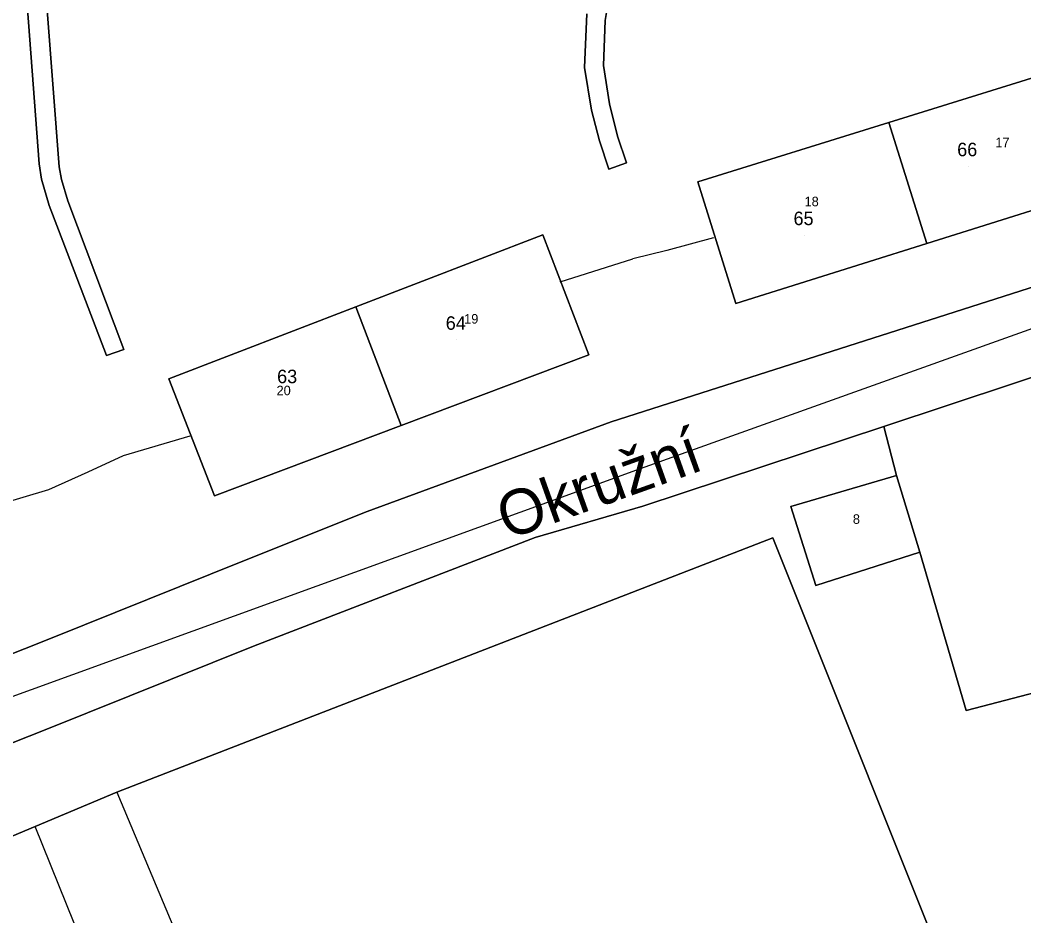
# Model space of a CAD drawing. Extents: x -873642 to -872917, y -1012962 to -1012567.
# Drawn here: x -873373.1 to -873283.8, y -1012828.2 to -1012748.5 of the extents above; entities that cross this region are included whole.
import ezdxf

# ---------------------------------------------------------------- set-up
doc = ezdxf.new("R2010")
doc.units = 0
for name, color, linetype in [('adresni_misto', 7, 'Continuous'), ('cisla_parcelni_kn', 7, 'Continuous'), ('cislo_domovni', 7, 'Continuous'), ('osy_ulic', 7, 'Continuous'), ('parcely_kn', 7, 'Continuous'), ('stavebni_objekty_bydleni', 7, 'Continuous'), ('stavebni_objekty_vyroba', 7, 'Continuous'), ('TRASY - zamereno', 7, 'Continuous'), ('ulice', 7, 'Continuous')]:
    doc.layers.add(name, color=color, linetype=linetype)

msp = doc.modelspace()

# ---------------------------------------------------------------- linework, layer by layer
at = {"layer": 'adresni_misto'}
for p, q in [((-873288.69, -1012761.56), (-873288.69, -1012761.56)), ((-873303.25, -1012767.69), (-873303.25, -1012767.69)), ((-873334.19, -1012777), (-873334.19, -1012777)), ((-873349.19, -1012781.75), (-873349.19, -1012781.75))]:
    msp.add_line(p, q, dxfattribs=at)
at = {"layer": 'osy_ulic'}
msp.add_lwpolyline([(-873411.85, -1012822.53), (-873317.85, -1012788.44), (-873277.23, -1012773.91), (-873252.76, -1012767.01), (-873201.18, -1012755.57), (-873115.6, -1012739.3), (-873104.65, -1012731.3), (-873088.93, -1012706.26), (-873080.41, -1012681.66), (-873071.61, -1012653.78), (-873070.57, -1012650.45), (-873066.08, -1012632.13), (-873063.74, -1012625.63), (-873059.56, -1012597.3)], dxfattribs=at)
at = {"layer": 'parcely_kn'}
for points in [[(-873320.46, -1012784.28), (-873268.07, -1012767.54), (-873249.92, -1012762.57), (-873226.73, -1012756.94), (-873186.64, -1012748.89), (-873149.68, -1012742.06), (-873135.84, -1012739.52), (-873124.72, -1012736.51), (-873113.32, -1012731.6), (-873103.81, -1012724.84), (-873095.71, -1012715.02), (-873089.72, -1012704.46), (-873086.77, -1012695.86), (-873085.73, -1012692.85), (-873081.52, -1012670.94), (-873077.58, -1012656.47), (-873075.63, -1012649.79), (-873072.81, -1012640.75), (-873068.46, -1012627.76), (-873067.09, -1012621.71)], [(-873320.46, -1012784.28), (-873268.07, -1012767.54), (-873249.92, -1012762.57), (-873226.73, -1012756.94), (-873186.64, -1012748.89), (-873149.68, -1012742.06), (-873135.84, -1012739.52), (-873124.72, -1012736.51), (-873113.32, -1012731.6), (-873103.81, -1012724.84), (-873095.71, -1012715.02), (-873089.72, -1012704.46), (-873086.77, -1012695.86), (-873085.73, -1012692.85), (-873081.52, -1012670.94), (-873077.58, -1012656.47), (-873075.63, -1012649.79), (-873072.81, -1012640.75), (-873068.46, -1012627.76), (-873067.09, -1012621.71)], [(-873492.26, -1012636.3), (-873470.15, -1012634.51), (-873474.09, -1012635.88), (-873476.25, -1012638.16), (-873476.91, -1012642.49), (-873474.55, -1012659.21), (-873473.95, -1012664.84), (-873471.34, -1012679.34), (-873470.31, -1012685.53), (-873467.35, -1012700.29), (-873461.39, -1012719.27), (-873456.13, -1012732.5), (-873430.5, -1012781.58), (-873414.44, -1012810.45), (-873408.91, -1012815.19), (-873407.03, -1012815.83), (-873405.77, -1012816.17), (-873403.3, -1012816.28), (-873400.05, -1012815.37), (-873370.19, -1012803.49), (-873353.25, -1012796.68), (-873342.17, -1012792.27), (-873320.46, -1012784.28)], [(-873492.26, -1012636.3), (-873470.15, -1012634.51), (-873474.09, -1012635.88), (-873476.25, -1012638.16), (-873476.91, -1012642.49), (-873474.55, -1012659.21), (-873473.95, -1012664.84), (-873471.34, -1012679.34), (-873470.31, -1012685.53), (-873467.35, -1012700.29), (-873461.39, -1012719.27), (-873456.13, -1012732.5), (-873430.5, -1012781.58), (-873414.44, -1012810.45), (-873408.91, -1012815.19), (-873407.03, -1012815.83), (-873405.77, -1012816.17), (-873403.3, -1012816.28), (-873400.05, -1012815.37), (-873370.19, -1012803.49), (-873353.25, -1012796.68), (-873342.17, -1012792.27), (-873320.46, -1012784.28)], [(-873267.15, -1012775.08), (-873296.21, -1012784.7), (-873317.65, -1012791.79), (-873327.22, -1012794.59), (-873352.28, -1012804.24), (-873370.67, -1012811.62), (-873407.44, -1012826.19), (-873420.81, -1012815.05), (-873432.2, -1012793.89), (-873433.76, -1012792.56), (-873435.3, -1012792.45), (-873437.28, -1012792.66), (-873438.97, -1012789.6), (-873437.44, -1012788.27), (-873436.61, -1012786.86), (-873438.55, -1012783.17), (-873447.85, -1012766.32), (-873454.18, -1012754.58), (-873460.09, -1012742.48), (-873462.37, -1012737.41), (-873469.44, -1012722.44), (-873475.56, -1012699.33), (-873477.8, -1012685.05)], [(-873267.15, -1012775.08), (-873296.21, -1012784.7), (-873317.65, -1012791.79), (-873327.22, -1012794.59), (-873352.28, -1012804.24), (-873370.67, -1012811.62), (-873407.44, -1012826.19), (-873420.81, -1012815.05), (-873432.2, -1012793.89), (-873433.76, -1012792.56), (-873435.3, -1012792.45), (-873437.28, -1012792.66), (-873438.97, -1012789.6), (-873437.44, -1012788.27), (-873436.61, -1012786.86), (-873438.55, -1012783.17), (-873447.85, -1012766.32), (-873454.18, -1012754.58), (-873460.09, -1012742.48), (-873462.37, -1012737.41), (-873469.44, -1012722.44), (-873475.56, -1012699.33), (-873477.8, -1012685.05)], [(-873372.72, -1012743.18), (-873371.35, -1012761.35), (-873371.16, -1012762.69), (-873370.48, -1012765.05), (-873369.65, -1012767.21), (-873365.37, -1012778.38), (-873363.83, -1012777.84), (-873368.81, -1012764.64), (-873369.36, -1012762.74), (-873369.57, -1012761.6), (-873371.72, -1012733.69)], [(-873371.72, -1012733.69), (-873369.57, -1012761.6), (-873369.36, -1012762.74), (-873368.81, -1012764.64), (-873363.83, -1012777.84), (-873365.37, -1012778.38), (-873369.65, -1012767.21), (-873370.48, -1012765.05), (-873371.16, -1012762.69), (-873371.35, -1012761.35), (-873372.72, -1012743.18)], [(-873372.72, -1012743.18), (-873371.35, -1012761.35), (-873371.16, -1012762.69), (-873370.48, -1012765.05), (-873369.65, -1012767.21), (-873365.37, -1012778.38), (-873363.83, -1012777.84), (-873368.81, -1012764.64), (-873369.36, -1012762.74), (-873369.57, -1012761.6), (-873371.72, -1012733.69)], [(-873371.72, -1012733.69), (-873369.57, -1012761.6), (-873369.36, -1012762.74), (-873368.81, -1012764.64), (-873363.83, -1012777.84), (-873365.37, -1012778.38), (-873369.65, -1012767.21), (-873370.48, -1012765.05), (-873371.16, -1012762.69), (-873371.35, -1012761.35), (-873372.72, -1012743.18)], [(-873322.63, -1012747.98), (-873322.84, -1012752.76), (-873322.22, -1012756.56), (-873321.51, -1012759.3), (-873320.68, -1012761.82), (-873319.1, -1012761.25), (-873319.91, -1012758.89), (-873320.61, -1012755.99), (-873321.15, -1012752.59), (-873321.02, -1012748.59), (-873320.43, -1012745.18)], [(-873320.43, -1012745.18), (-873321.02, -1012748.59), (-873321.15, -1012752.59), (-873320.61, -1012755.99), (-873319.91, -1012758.89), (-873319.1, -1012761.25), (-873320.68, -1012761.82), (-873321.51, -1012759.3), (-873322.22, -1012756.56), (-873322.84, -1012752.76), (-873322.63, -1012747.98)], [(-873322.63, -1012747.98), (-873322.84, -1012752.76), (-873322.22, -1012756.56), (-873321.51, -1012759.3), (-873320.68, -1012761.82), (-873319.1, -1012761.25), (-873319.91, -1012758.89), (-873320.61, -1012755.99), (-873321.15, -1012752.59), (-873321.02, -1012748.59), (-873320.43, -1012745.18)], [(-873320.43, -1012745.18), (-873321.02, -1012748.59), (-873321.15, -1012752.59), (-873320.61, -1012755.99), (-873319.91, -1012758.89), (-873319.1, -1012761.25), (-873320.68, -1012761.82), (-873321.51, -1012759.3), (-873322.22, -1012756.56), (-873322.84, -1012752.76), (-873322.63, -1012747.98)], [(-873491.56, -1012871.97), (-873407.44, -1012826.19), (-873370.67, -1012811.62), (-873352.28, -1012804.24), (-873327.22, -1012794.59), (-873317.65, -1012791.79), (-873296.21, -1012784.7), (-873295.08, -1012789.07), (-873304.48, -1012791.83), (-873302.28, -1012798.85), (-873296.89, -1012797.13), (-873293, -1012795.88), (-873288.89, -1012809.97), (-873206.66, -1012788.54), (-873209.55, -1012779.29), (-873212.49, -1012767.05), (-873213.62, -1012762.14), (-873185.58, -1012756.25), (-873148.18, -1012749.22)], [(-873491.56, -1012871.97), (-873407.44, -1012826.19), (-873370.67, -1012811.62), (-873352.28, -1012804.24), (-873327.22, -1012794.59), (-873317.65, -1012791.79), (-873296.21, -1012784.7), (-873295.08, -1012789.07), (-873304.48, -1012791.83), (-873302.28, -1012798.85), (-873296.89, -1012797.13), (-873293, -1012795.88), (-873288.89, -1012809.97), (-873206.66, -1012788.54), (-873209.55, -1012779.29), (-873212.49, -1012767.05), (-873213.62, -1012762.14), (-873185.58, -1012756.25), (-873148.18, -1012749.22)], [(-873268.07, -1012767.54), (-873320.46, -1012784.28), (-873342.17, -1012792.27), (-873353.25, -1012796.68), (-873370.19, -1012803.49), (-873400.05, -1012815.37)], [(-873268.07, -1012767.54), (-873320.46, -1012784.28), (-873342.17, -1012792.27), (-873353.25, -1012796.68), (-873370.19, -1012803.49), (-873400.05, -1012815.37)]]:
    msp.add_lwpolyline(points, dxfattribs=at)
for points in [[(-873275.41, -1012763.1), (-873278.77, -1012752.39), (-873295.77, -1012757.66), (-873312.76, -1012762.93), (-873309.38, -1012773.75), (-873292.4, -1012768.43)], [(-873275.41, -1012763.1), (-873278.77, -1012752.39), (-873295.77, -1012757.66), (-873312.76, -1012762.93), (-873309.38, -1012773.75), (-873292.4, -1012768.43)], [(-873295.77, -1012757.66), (-873278.77, -1012752.39), (-873275.41, -1012763.1), (-873292.4, -1012768.43)], [(-873295.77, -1012757.66), (-873278.77, -1012752.39), (-873275.41, -1012763.1), (-873292.4, -1012768.43)], [(-873312.76, -1012762.93), (-873295.77, -1012757.66), (-873292.4, -1012768.43), (-873309.38, -1012773.75)], [(-873312.76, -1012762.93), (-873295.77, -1012757.66), (-873292.4, -1012768.43), (-873309.38, -1012773.75)], [(-873267.15, -1012775.08), (-873258.26, -1012772.76), (-873242.16, -1012768.49), (-873213.62, -1012762.14), (-873212.49, -1012767.05), (-873280.88, -1012784.53), (-873277.69, -1012796.87), (-873209.55, -1012779.29), (-873206.66, -1012788.54), (-873288.89, -1012809.97), (-873293, -1012795.88), (-873295.08, -1012789.07), (-873296.21, -1012784.7)], [(-873267.15, -1012775.08), (-873258.26, -1012772.76), (-873242.16, -1012768.49), (-873213.62, -1012762.14), (-873212.49, -1012767.05), (-873280.88, -1012784.53), (-873277.69, -1012796.87), (-873209.55, -1012779.29), (-873206.66, -1012788.54), (-873288.89, -1012809.97), (-873293, -1012795.88), (-873295.08, -1012789.07), (-873296.21, -1012784.7)], [(-873339.15, -1012784.62), (-873322.45, -1012778.33), (-873326.56, -1012767.66), (-873343.19, -1012774.07), (-873359.82, -1012780.47), (-873355.76, -1012790.87)], [(-873339.15, -1012784.62), (-873322.45, -1012778.33), (-873326.56, -1012767.66), (-873343.19, -1012774.07), (-873359.82, -1012780.47), (-873355.76, -1012790.87)], [(-873322.45, -1012778.33), (-873339.15, -1012784.62), (-873343.19, -1012774.07), (-873326.56, -1012767.66)], [(-873322.45, -1012778.33), (-873339.15, -1012784.62), (-873343.19, -1012774.07), (-873326.56, -1012767.66)], [(-873359.82, -1012780.47), (-873343.19, -1012774.07), (-873339.15, -1012784.62), (-873355.76, -1012790.87)], [(-873359.82, -1012780.47), (-873343.19, -1012774.07), (-873339.15, -1012784.62), (-873355.76, -1012790.87)], [(-873304.48, -1012791.83), (-873295.08, -1012789.07), (-873293, -1012795.88), (-873296.89, -1012797.13), (-873302.28, -1012798.85)], [(-873304.48, -1012791.83), (-873295.08, -1012789.07), (-873293, -1012795.88), (-873296.89, -1012797.13), (-873302.28, -1012798.85)], [(-873379.34, -1012875.83), (-873373.58, -1012889.78), (-873355.03, -1012878.22), (-873289.09, -1012837.11), (-873306.1, -1012794.62), (-873364.45, -1012817.23), (-873371.7, -1012820.28), (-873376.39, -1012822.23), (-873378.27, -1012823.02), (-873378.61, -1012822.17), (-873388.38, -1012826.03), (-873398.8, -1012830.22), (-873398.3, -1012831.4), (-873382.99, -1012867.41)], [(-873379.34, -1012875.83), (-873373.58, -1012889.78), (-873355.03, -1012878.22), (-873289.09, -1012837.11), (-873306.1, -1012794.62), (-873364.45, -1012817.23), (-873371.7, -1012820.28), (-873376.39, -1012822.23), (-873378.27, -1012823.02), (-873378.61, -1012822.17), (-873388.38, -1012826.03), (-873398.8, -1012830.22), (-873398.3, -1012831.4), (-873382.99, -1012867.41)], [(-873364.45, -1012817.23), (-873306.1, -1012794.62), (-873289.09, -1012837.11), (-873355.03, -1012878.22), (-873364.42, -1012853.62), (-873375.46, -1012858.04), (-873381.76, -1012842.3), (-873370.46, -1012837.78), (-873376.39, -1012822.23), (-873371.7, -1012820.28)], [(-873364.45, -1012817.23), (-873306.1, -1012794.62), (-873289.09, -1012837.11), (-873355.03, -1012878.22), (-873364.42, -1012853.62), (-873375.46, -1012858.04), (-873381.76, -1012842.3), (-873370.46, -1012837.78), (-873376.39, -1012822.23), (-873371.7, -1012820.28)]]:
    msp.add_lwpolyline(points, close=True, dxfattribs=at)
at = {"layer": 'stavebni_objekty_bydleni'}
for points in [[(-873312.76, -1012762.93), (-873295.77, -1012757.66), (-873278.77, -1012752.39), (-873275.41, -1012763.1), (-873292.4, -1012768.43), (-873309.38, -1012773.75)], [(-873359.82, -1012780.47), (-873343.19, -1012774.07), (-873326.56, -1012767.66), (-873322.45, -1012778.33), (-873339.15, -1012784.62), (-873355.76, -1012790.87)]]:
    msp.add_lwpolyline(points, close=True, dxfattribs=at)
at = {"layer": 'stavebni_objekty_vyroba'}
for points in [[(-873293, -1012795.88), (-873296.89, -1012797.13), (-873302.28, -1012798.85), (-873304.48, -1012791.83), (-873295.08, -1012789.07)], [(-873375.46, -1012858.04), (-873381.76, -1012842.3), (-873370.46, -1012837.78), (-873365.46, -1012835.78), (-873371.7, -1012820.28), (-873364.45, -1012817.23), (-873357.84, -1012832.99), (-873358.79, -1012833.39), (-873356.72, -1012838.55), (-873351.7, -1012836.52), (-873350.19, -1012840.26), (-873355.22, -1012842.29), (-873352.58, -1012848.89), (-873364.42, -1012853.62)]]:
    msp.add_lwpolyline(points, close=True, dxfattribs=at)
at = {"layer": 'TRASY - zamereno'}
for p, q in [((-873311.38, -1012767.93), (-873315.52, -1012769.06)), ((-873315.52, -1012769.06), (-873318.55, -1012769.79)), ((-873324.999, -1012771.826), (-873318.55, -1012769.79)), ((-873363.86, -1012787.29), (-873357.915, -1012785.548)), ((-873367.01, -1012788.74), (-873363.86, -1012787.29)), ((-873370.51, -1012790.31), (-873367.01, -1012788.74)), ((-873375.47, -1012791.79), (-873370.51, -1012790.31))]:
    msp.add_line(p, q, dxfattribs=at)

# ---------------------------------------------------------------- texts
at = {"layer": 'cisla_parcelni_kn'}
for s, p in [('17', (-873286.302, -1012759.863)), ('17', (-873286.302, -1012759.863)), ('18', (-873303.271, -1012765.113)), ('18', (-873303.271, -1012765.113)), ('19', (-873333.552, -1012775.55)), ('19', (-873333.552, -1012775.55)), ('20', (-873350.24, -1012781.925)), ('20', (-873350.24, -1012781.925)), ('8', (-873298.971, -1012793.363)), ('8', (-873298.971, -1012793.363))]:
    msp.add_text(s, height=0.85, dxfattribs=at).set_placement(p)
at = {"layer": 'cislo_domovni'}
for s, p in [('66', (-873289.69, -1012760.66)), ('65', (-873304.25, -1012766.79)), ('64', (-873335.19, -1012776.1)), ('63', (-873350.19, -1012780.85))]:
    msp.add_text(s, height=1.2, dxfattribs=at).set_placement(p)
at = {"layer": 'ulice'}
msp.add_text('Okružní', height=4, rotation=19.68241, dxfattribs=at).set_placement((-873329.722, -1012794.811))

doc.saveas('drawing.dxf')
